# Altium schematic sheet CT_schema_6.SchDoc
size 371 x 245 mm
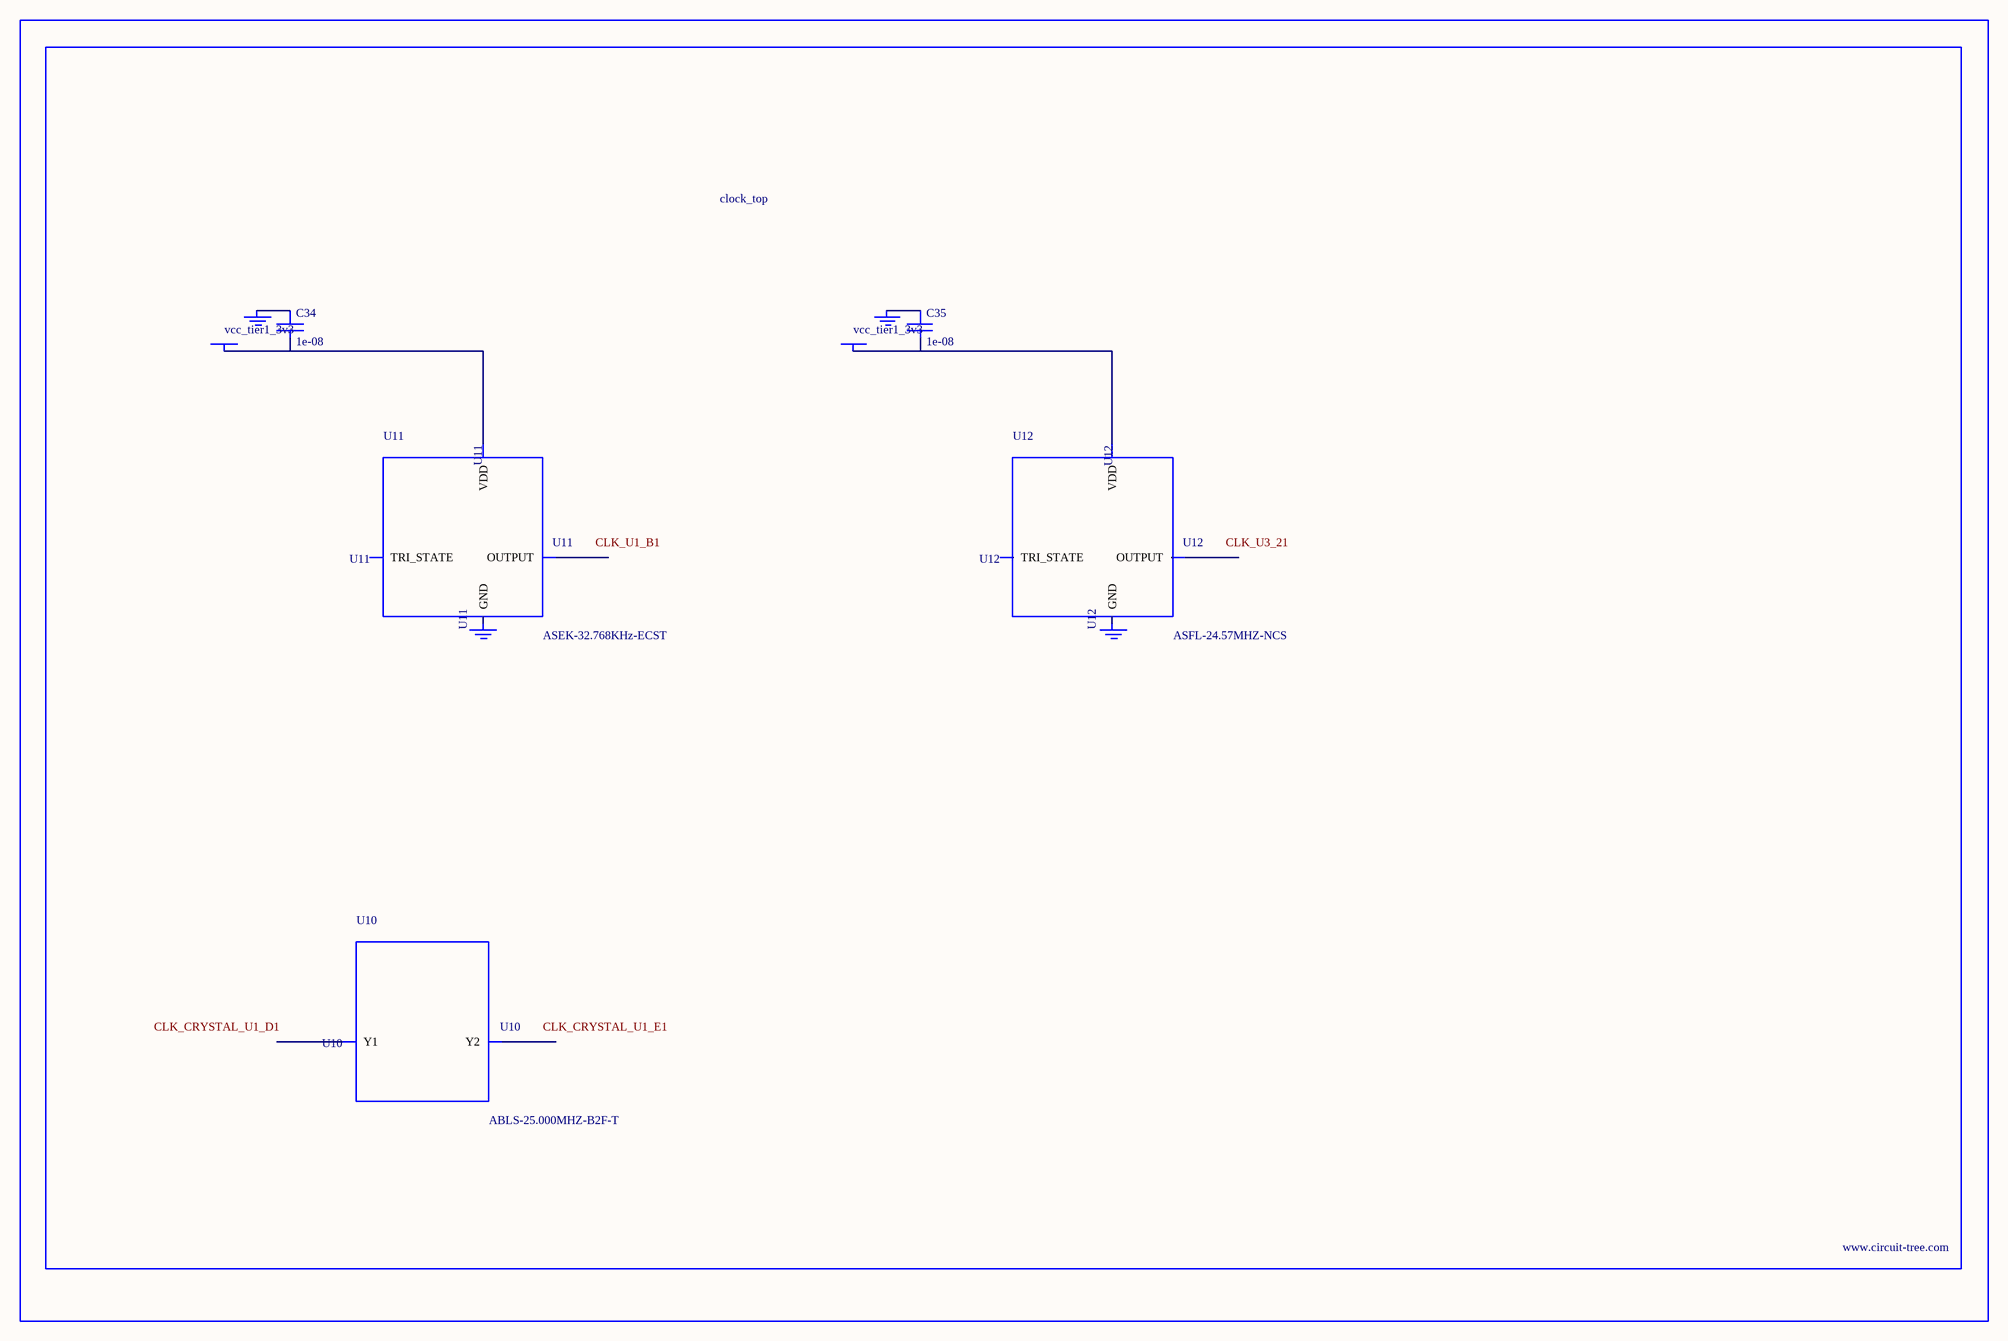
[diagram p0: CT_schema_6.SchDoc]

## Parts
BORDER5  (no value)
C34  1e-08  [C0402]
C35  1e-08  [C0402]
GND_INSTANCE_5_0  (no value)
GND_INSTANCE_5_1  (no value)
GND_INSTANCE_5_2  (no value)
GND_INSTANCE_5_3  (no value)
POWER_INSTANCE_5_0  vcc_tier1_3v3
POWER_INSTANCE_5_1  vcc_tier1_3v3
U10  ABLS-25.000MHZ-B2F-T  [ABLS-25.000MHZ-B2F-T]
U11  ASEK-32.768KHz-ECST  [ASEK]
U12  ASFL-24.57MHZ-NCS  [ASFL1]

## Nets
NetC34_1: C34.1 GND_INSTANCE_5_0.0(GND)
NetC34_2: C34.2 POWER_INSTANCE_5_0.0(PWR) U11.4(VDD)
NetC35_1: C35.1 GND_INSTANCE_5_2.0(GND)
NetC35_2: C35.2 POWER_INSTANCE_5_1.0(PWR) U12.4(VDD)

Not connected (* = marked no-connect by the designer): GND_INSTANCE_5_1 0(GND); GND_INSTANCE_5_3 0(GND); U10 1(Y1) 2(Y2); U11 1(TRI_STATE) 2(GND) 3(OUTPUT); U12 1(TRI_STATE) 2(GND) 3(OUTPUT)

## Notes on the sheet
- Labels drawn without touching a wire or pin: CLK_CRYSTAL_U1_D1, CLK_CRYSTAL_U1_E1, CLK_U1_B1, CLK_U3_21

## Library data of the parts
BORDER5 = BORDER_PAGE5
C34 C35 = C0402C103K3RAC
GND_INSTANCE_5_0-GND_INSTANCE_5_3 = GND
POWER_INSTANCE_5_0 POWER_INSTANCE_5_1 = PWR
